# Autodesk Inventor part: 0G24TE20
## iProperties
Created: 2007-01
Description: 3000x1500x20
Document SubType Name: Blech
Designer: R.Pilz
Part Number: 0G24TE20
ArtNrPrefix: HZ
ArtNrAuto: 0
EDVNum=ArtNr: 0
Bez=Mat: 0
ArtNrBackSpace: 0
EDVNrBackSpace: 0
EDVNrAuto: 0
ProdGruppe: ÜKWW
ProdBezeichnung: Blende
ArtNr: HZG24TE20
EDVNr: L4321
KommaZuschnitt: 0
Zeichnungsnummer: 0G24 TE ST
Konstrukteur: R.Pilz
Erstellungsdatum: 10.01.2007
GesGewicht: 1,2kg
Material: Standard
Title: Platte
Author: R.Pilz
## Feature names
1. Abgeleiteter Körper1 [Tagging]
